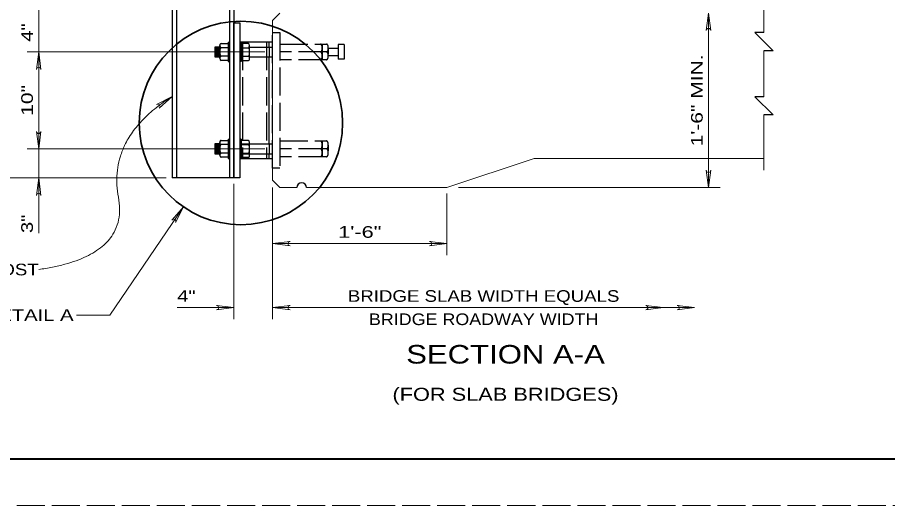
# Model space of a CAD drawing. Extents: x 1285 to 1427, y 1365 to 1427.
# Drawn here: x 1387.58 to 1400.06, y 1397.33 to 1404.33 of the extents above; entities that cross this region are included whole.
import ezdxf
from ezdxf.enums import TextEntityAlignment as Align

# ---------------------------------------------------------------- set-up
doc = ezdxf.new("R2010")
doc.units = 0
doc.header["$LTSCALE"] = 0.067
doc.linetypes.add('LONG_DASHED', pattern=[7.5, 6, -1.5])
for name, color, linetype, lineweight in [('1', 7, 'Continuous', 40), ('42', 7, 'Continuous', 25), ('44', 7, 'Continuous', 13)]:
    doc.layers.add(name, color=color, linetype=linetype, lineweight=lineweight)

msp = doc.modelspace()

# ---------------------------------------------------------------- linework, layer by layer
at = {"layer": '1', "linetype": 'LONG_DASHED', "lineweight": 13}
msp.add_lwpolyline([(1381.33333, 1426.66667), (1426.66667, 1426.66667), (1426.66667, 1397.33333), (1381.33333, 1397.33333)], close=True, dxfattribs=at)
at = {"layer": '1'}
msp.add_lwpolyline([(1384, 1426), (1426, 1426), (1426, 1398), (1384, 1398)], close=True, dxfattribs=at)
at = {"layer": '42'}
for p, q in [((1389.79978, 1409.02644), (1389.79978, 1402.03044)), ((1389.863, 1409.02644), (1389.863, 1402.03044)), ((1390.62267, 1409.02644), (1390.62267, 1402.03044)), ((1390.43178, 1403.89667), (1390.43178, 1403.77511)), ((1390.44911, 1403.89667), (1390.44911, 1403.77511)), ((1390.46644, 1403.89667), (1390.46644, 1403.77511)), ((1390.48389, 1403.74478), (1390.48389, 1403.92711)), ((1390.50122, 1403.95744), (1390.60544, 1403.95744)), ((1390.60533, 1403.89667), (1390.50122, 1403.89667)), ((1390.60544, 1403.97478), (1390.60533, 1403.69711)), ((1390.60544, 1403.97478), (1390.62267, 1403.97478)), ((1391.24144, 1403.97489), (1390.77278, 1403.97489)), ((1390.79, 1403.97478), (1390.77278, 1403.97478)), ((1390.79, 1403.97478), (1390.79011, 1403.69711)), ((1390.89422, 1403.95744), (1390.79, 1403.95744)), ((1390.79011, 1403.89667), (1390.89422, 1403.89667)), ((1390.91156, 1403.74478), (1390.91156, 1403.92711)), ((1390.91156, 1403.90533), (1391.24144, 1403.90533)), ((1391.18944, 1403.90533), (1391.18944, 1403.97489)), ((1390.60533, 1403.77511), (1390.50122, 1403.77511)), ((1390.79011, 1403.77511), (1390.89422, 1403.77511)), ((1390.60533, 1403.71444), (1390.50122, 1403.71444)), ((1390.60533, 1403.69711), (1390.62267, 1403.69711)), ((1390.79011, 1403.69711), (1390.77278, 1403.69711)), ((1390.79011, 1403.71444), (1390.89422, 1403.71444)), ((1390.91156, 1403.76644), (1391.24133, 1403.76644)), ((1391.18944, 1402.51644), (1391.18944, 1403.76644)), ((1390.48389, 1402.35589), (1390.48389, 1402.53822)), ((1390.50122, 1402.56856), (1390.60544, 1402.56856)), ((1390.60544, 1402.58589), (1390.60533, 1402.30822)), ((1390.60544, 1402.58589), (1390.62267, 1402.58589)), ((1390.79, 1402.58589), (1390.77278, 1402.58589)), ((1390.79, 1402.58589), (1390.79011, 1402.30822)), ((1390.89422, 1402.56856), (1390.79, 1402.56856)), ((1390.91156, 1402.35589), (1390.91156, 1402.53822)), ((1390.43178, 1402.50778), (1390.43178, 1402.38622)), ((1390.44911, 1402.50778), (1390.44911, 1402.38622)), ((1390.46644, 1402.50778), (1390.46644, 1402.38622)), ((1390.60533, 1402.50778), (1390.50122, 1402.50778)), ((1390.79011, 1402.50778), (1390.89422, 1402.50778)), ((1390.91156, 1402.51644), (1391.24133, 1402.51644)), ((1390.60533, 1402.38622), (1390.50122, 1402.38622)), ((1390.60533, 1402.32556), (1390.50122, 1402.32556)), ((1390.60533, 1402.30822), (1390.62267, 1402.30822)), ((1390.79011, 1402.30822), (1390.77278, 1402.30822)), ((1390.79011, 1402.38622), (1390.89422, 1402.38622)), ((1390.79011, 1402.32556), (1390.89422, 1402.32556)), ((1390.91156, 1402.37756), (1391.24133, 1402.37756)), ((1391.18944, 1402.30822), (1391.18944, 1402.37756))]:
    msp.add_line(p, q, dxfattribs=at)
at = {"layer": '42', "lineweight": 13}
for p, q in [((1398.28767, 1404.90533), (1398.28767, 1404.11433)), ((1391.24133, 1404.28722), (1391.34544, 1404.39144)), ((1391.24133, 1404.28722), (1391.24133, 1401.99567)), ((1398.28767, 1403.85378), (1398.28767, 1403.19311)), ((1398.28767, 1402.93256), (1398.28767, 1402.14144)), ((1391.34544, 1401.89144), (1391.24133, 1401.99567)), ((1391.34544, 1401.89144), (1391.58856, 1401.89144)), ((1391.72744, 1401.89144), (1393.74133, 1401.89144))]:
    msp.add_line(p, q, dxfattribs=at)
at = {"layer": '42', "linetype": 'LONG_DASHED'}
for p, q in [((1390.80756, 1403.97489), (1390.80756, 1402.30822)), ((1391.15467, 1403.97489), (1391.15467, 1402.30822)), ((1391.18944, 1403.90533), (1391.18944, 1403.76644)), ((1391.34544, 1403.94889), (1392.01389, 1403.94889)), ((1391.95311, 1403.94889), (1391.95311, 1403.88822)), ((1392.26556, 1403.94033), (1392.17878, 1403.94033)), ((1392.17878, 1403.94033), (1392.17878, 1403.732)), ((1392.01389, 1403.836), (1391.34544, 1403.836)), ((1392.03989, 1403.88822), (1392.17878, 1403.88822)), ((1392.03989, 1403.88822), (1392.03989, 1403.80511)), ((1392.03989, 1403.784), (1392.17878, 1403.784)), ((1392.01389, 1403.72311), (1391.34544, 1403.72311)), ((1391.34544, 1402.56), (1392.01389, 1402.56)), ((1391.95311, 1402.56), (1391.95311, 1402.49933)), ((1390.77278, 1402.51644), (1390.91156, 1402.51644)), ((1391.18944, 1402.51644), (1391.18944, 1402.37756)), ((1392.01389, 1402.44711), (1391.34544, 1402.44711)), ((1392.03989, 1402.49933), (1392.03989, 1402.41622)), ((1390.77278, 1402.37756), (1390.91156, 1402.37756)), ((1392.01389, 1402.33422), (1391.34544, 1402.33422))]:
    msp.add_line(p, q, dxfattribs=at)
at = {"layer": '42'}
for points in [[(1390.68589, 1409.02644), (1390.68589, 1402.03044), (1389.79978, 1402.03044)], [(1398.28767, 1404.11433), (1398.15744, 1404.11433), (1398.41778, 1403.85378), (1398.28767, 1403.85378)], [(1390.48389, 1403.90533), (1390.41444, 1403.90533), (1390.41444, 1403.76644), (1390.48389, 1403.76644)], [(1390.77278, 1403.97489), (1390.77278, 1402.30822), (1391.24133, 1402.30822)], [(1398.28767, 1403.19311), (1398.15744, 1403.19311), (1398.41778, 1402.93256), (1398.28767, 1402.93256)], [(1390.48389, 1402.51644), (1390.41444, 1402.51644), (1390.41444, 1402.37756), (1390.48389, 1402.37756)]]:
    msp.add_lwpolyline(points, dxfattribs=at)
msp.add_lwpolyline([(1390.68589, 1404.25267), (1390.77278, 1404.25267), (1390.77278, 1402.03044), (1390.68589, 1402.03044)], close=True, dxfattribs=at)
at = {"layer": '42', "linetype": 'LONG_DASHED'}
msp.add_lwpolyline([(1391.24133, 1404.11378), (1391.34544, 1404.11378), (1391.34544, 1402.16933), (1391.24133, 1402.16933)], close=True, dxfattribs=at)
for points in [[(1392.26556, 1403.94033), (1392.26556, 1403.732), (1392.17878, 1403.732)], [(1391.95311, 1403.88822), (1391.95311, 1403.784), (1391.95311, 1403.72311)], [(1391.95311, 1402.49933), (1391.95311, 1402.39511), (1391.95311, 1402.33422)]]:
    msp.add_lwpolyline(points, dxfattribs=at)
at = {"layer": '42', "lineweight": 13}
msp.add_lwpolyline([(1393.74133, 1401.89144), (1394.99133, 1402.30811), (1398.28767, 1402.30811)], dxfattribs=at)
at = {"layer": '42'}
msp.add_arc((1391.658, 1401.89144), 0.06944, 0, 180, dxfattribs=at)
for centre, major_axis, ratio, start_param, end_param in [((1390.50122, 1403.92711), (0, -0.03033), 0.571429, 3.14159265, 6.28318531), ((1390.50122, 1403.83589), (0, 0.06078), 0.285192, 6.28318531, 9.42477796), ((1390.89422, 1403.92711), (0, -0.03033), 0.571429, 6.28318531, 9.42477796), ((1390.89422, 1403.83589), (0, 0.06078), 0.285192, 3.14159265, 6.28318531), ((1390.50122, 1403.74478), (0, 0.03033), 0.571429, 6.28318531, 9.42477796), ((1390.89422, 1403.74478), (0, 0.03033), 0.571429, 3.14159265, 6.28318531), ((1390.50122, 1402.53822), (0, -0.03033), 0.571429, 3.14159265, 6.28318531), ((1390.89422, 1402.53822), (0, -0.03033), 0.571429, 6.28318531, 9.42477796), ((1390.50122, 1402.447), (0, 0.06078), 0.285192, 6.28318531, 9.42477796), ((1390.89422, 1402.447), (0, 0.06078), 0.285192, 3.14159265, 6.28318531), ((1390.50122, 1402.35589), (0, 0.03033), 0.571429, 6.28318531, 9.42477796), ((1390.89422, 1402.35589), (0, 0.03033), 0.571429, 3.14159265, 6.28318531)]:
    msp.add_ellipse(centre, major_axis=major_axis, ratio=ratio, start_param=start_param, end_param=end_param, dxfattribs=at)
at = {"layer": '42', "linetype": 'LONG_DASHED'}
for centre, start_param, end_param in [((1391.92706, 1403.89247), 1.49443008, 3.14159265), ((1392.01391, 1403.89247), 1.49443008, 3.14159265), ((1391.92706, 1403.89247), 6.28318531, 7.77761538), ((1391.92706, 1403.7796), 1.64880818, 3.14159265), ((1391.92706, 1403.7796), 6.28318531, 7.93199349), ((1392.01391, 1403.89247), 6.28318531, 7.77761538), ((1392.01391, 1403.7796), 1.64880818, 3.14159265), ((1392.01391, 1403.7796), 6.28318531, 7.93199349), ((1391.92706, 1402.50358), 1.49443008, 3.14159265), ((1392.01391, 1402.50358), 1.49443008, 3.14159265), ((1391.92706, 1402.50358), 6.28318531, 7.77761538), ((1391.92706, 1402.39071), 1.64880818, 3.14159265), ((1392.01391, 1402.50358), 6.28318531, 7.77761538), ((1392.01391, 1402.39071), 1.64880818, 3.14159265), ((1391.92706, 1402.39071), 6.28318531, 7.93199349), ((1392.01391, 1402.39071), 6.28318531, 7.93199349)]:
    msp.add_ellipse(centre, major_axis=(0, -0.05644), ratio=0.461034, start_param=start_param, end_param=end_param, dxfattribs=at)
at = {"layer": '44'}
for p, q in [((1397.49256, 1404.39144), (1397.46133, 1404.14144)), ((1397.49256, 1401.89144), (1397.49256, 1404.39144)), ((1397.52378, 1404.14144), (1397.49256, 1404.39144)), ((1391.12811, 1403.83589), (1387.71967, 1403.83589)), ((1387.88633, 1403.83589), (1387.85511, 1403.58589)), ((1387.91756, 1403.58589), (1387.88633, 1403.83589)), ((1389.79967, 1403.19956), (1389.57722, 1403.08111)), ((1389.61322, 1403.03011), (1389.79967, 1403.19956)), ((1387.85511, 1402.697), (1387.88633, 1402.447)), ((1387.88633, 1402.447), (1387.91756, 1402.697)), ((1391.12811, 1402.447), (1387.71967, 1402.447)), ((1389.71633, 1402.03033), (1386.71967, 1402.03033)), ((1387.88633, 1402.03033), (1387.85511, 1401.78033)), ((1387.88633, 1401.23967), (1387.88633, 1402.03033)), ((1387.91756, 1401.78033), (1387.88633, 1402.03033)), ((1397.46133, 1402.14144), (1397.49256, 1401.89144)), ((1397.49256, 1401.89144), (1397.52378, 1402.14144)), ((1390.68589, 1401.947), (1390.68589, 1400.00422)), ((1391.24122, 1401.89133), (1391.24122, 1400.00422)), ((1391.24133, 1401.89144), (1391.24133, 1400.92233)), ((1393.74133, 1401.80811), (1393.74133, 1400.92233)), ((1393.908, 1401.89144), (1397.65922, 1401.89144)), ((1389.84889, 1401.38956), (1389.964, 1401.61367)), ((1391.49133, 1401.12022), (1391.24133, 1401.089)), ((1391.24133, 1401.089), (1393.74133, 1401.089)), ((1391.24133, 1401.089), (1391.49133, 1401.05778)), ((1393.74133, 1401.089), (1393.49133, 1401.12022)), ((1393.49133, 1401.05778), (1393.74133, 1401.089)), ((1390.68589, 1400.17089), (1389.87233, 1400.17089)), ((1390.68589, 1400.17089), (1390.43589, 1400.20211)), ((1390.43589, 1400.13967), (1390.68589, 1400.17089)), ((1391.49122, 1400.20211), (1391.24122, 1400.17089)), ((1397.29367, 1400.17089), (1391.24122, 1400.17089)), ((1391.24122, 1400.17089), (1391.49122, 1400.13967)), ((1396.84167, 1400.17089), (1396.59167, 1400.20211)), ((1396.59167, 1400.13967), (1396.84167, 1400.17089)), ((1397.29367, 1400.17089), (1397.04367, 1400.20211)), ((1397.04367, 1400.13967), (1397.29367, 1400.17089))]:
    msp.add_line(p, q, dxfattribs=at)
for points in [[(1387.88633, 1409.04422), (1387.88633, 1407.72478), (1387.88633, 1404.39144), (1387.88633, 1403.83589), (1387.88633, 1402.447), (1387.88633, 1402.03033)], [(1388.42767, 1400.06456), (1388.90656, 1400.06456), (1389.964, 1401.61367), (1389.79722, 1401.42478)]]:
    msp.add_lwpolyline(points, dxfattribs=at)
at = {"layer": '44', "lineweight": 35}
msp.add_circle((1390.78622, 1402.81811), 1.45833, dxfattribs=at)
at = {"layer": '44'}
for centre, start, end in [((1397.49256, 1404.14144), 0, 180), ((1387.88633, 1403.58589), 0, 180), ((1389.59522, 1403.05567), 305.13789, 125.13789), ((1387.88633, 1402.697), 180, 0), ((1397.49256, 1402.14144), 180, 0), ((1387.88633, 1401.78033), 0, 180), ((1389.82305, 1401.40719), 325.68202, 145.68202), ((1391.49133, 1401.089), 90, 270), ((1393.49133, 1401.089), 270, 90), ((1390.43589, 1400.17089), 270, 90), ((1391.49122, 1400.17089), 90, 270), ((1396.59167, 1400.17089), 270, 90), ((1397.04367, 1400.17089), 270, 90)]:
    msp.add_arc(centre, 0.03122, start, end, dxfattribs=at)
msp.add_open_spline([(1387.88633, 1400.71689), (1389.18911, 1400.90511), (1388.86967, 1402.60578), (1389.79967, 1403.19956)], degree=2, dxfattribs=at)

# ---------------------------------------------------------------- texts
for s, width, p in [('4"', 1.3, (1387.803, 1404.11372)), ('1\'-6" MIN.', 1.35, (1397.40922, 1403.14144)), ('10"', 1.35, (1387.803, 1403.1415))]:
    msp.add_text(s, height=0.1667, rotation=90, dxfattribs=dict(at, width=width)).set_placement(p, align=Align.CENTER)
at = {"layer": '44', "width": 1.3}
msp.add_text('3"', height=0.1667, rotation=90, dxfattribs=at).set_placement((1387.803, 1401.23967))
at = {"layer": '44'}
for s, height, width, p in [('1\'-6"', 0.1667, 1.4, (1392.49139, 1401.17233)), ('BRIDGE SLAB WIDTH EQUALS', 0.1667, 1.2, (1394.26744, 1400.25422)), ('BRIDGE ROADWAY WIDTH', 0.1667, 1.15, (1394.26744, 1399.92089)), ('SECTION A-A', 0.2667, 1.25, (1394.58117, 1399.36878)), ('(FOR SLAB BRIDGES)', 0.1867, 1.25, (1394.58111, 1398.83533))]:
    msp.add_text(s, height=height, dxfattribs=dict(at, width=width)).set_placement(p, align=Align.CENTER)
for s, width, p in [('W6x25 POST', 1.2, (1387.88633, 1400.63356)), ('SEE DETAIL A', 1.3, (1388.386, 1399.98122))]:
    msp.add_text(s, height=0.1667, dxfattribs=dict(at, width=width)).set_placement(p, align=Align.RIGHT)
at = {"layer": '44', "width": 1.3}
msp.add_text('4"', height=0.1667, dxfattribs=at).set_placement((1389.87233, 1400.25422))

doc.saveas('drawing.dxf')
